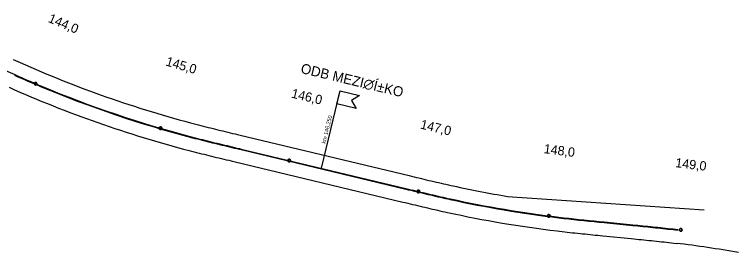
# Model space of a CAD drawing. Extents: x -670810 to -649614, y -1131928 to -1115069.
# Drawn here: x -655068 to -649614, y -1131928 to -1130133 of the extents above; entities that cross this region are included whole.
import ezdxf

# ---------------------------------------------------------------- set-up
doc = ezdxf.new("R2010")
doc.units = 0
for name, color, linetype in [('519 Var SK-4 Praporky stanic', 7, 'Continuous'), ('hranice_VRT_ZUR_Vysocina', 7, 'Continuous'), ('Situace - Osa koleje 2D', 7, 'Continuous'), ('Situace - Osa koleje tunel 2D', 7, 'Continuous'), ('Staničení - hlavní staničení + kolečka 1k', 7, 'Continuous')]:
    doc.layers.add(name, color=color, linetype=linetype)

# ---------------------------------------------------------------- blocks, each defined once
blk = doc.blocks.new('_U127')
at = {"layer": '519 Var SK-4 Praporky stanic'}
blk.add_line((-45.8, -299.9), (-45.8, 299.9), dxfattribs=at)
blk.add_lwpolyline([(-45.8, 299.9), (104.2, 299.9), (54.2, 249.9), (104.2, 199.9), (-45.8, 199.9)], close=True, dxfattribs=at)
blk.add_text('km 146,250', height=30, rotation=90, dxfattribs=at).set_placement((-59.2, -114))
blk = doc.blocks.new('_U126')
at = {"layer": '519 Var SK-4 Praporky stanic'}
blk.add_blockref('_U127', (45.8, -87.5), dxfattribs=at)
blk.add_text('ODB MEZI∅Í±KO', height=75, dxfattribs=at).set_placement((-325.1, 274.9))
blk = doc.blocks.new('Sit10Kruh_121')
at = {"layer": 'Staničení - hlavní staničení + kolečka 1k'}
blk.add_lwpolyline([(10, 0), (10, 0.6), (9.9, 1.3), (9.8, 1.9), (9.7, 2.5), (9.5, 3.1), (9.3, 3.7), (9, 4.3), (8.8, 4.8), (8.4, 5.4), (8.1, 5.9), (7.7, 6.4), (7.3, 6.8), (6.8, 7.3), (6.4, 7.7), (5.9, 8.1), (5.4, 8.4), (4.8, 8.8), (4.3, 9), (3.7, 9.3), (3.1, 9.5), (2.5, 9.7), (1.9, 9.8), (1.3, 9.9), (0.6, 10), (0, 10), (-0.6, 10), (-1.3, 9.9), (-1.9, 9.8), (-2.5, 9.7), (-3.1, 9.5), (-3.7, 9.3), (-4.3, 9), (-4.8, 8.8), (-5.4, 8.4), (-5.9, 8.1), (-6.4, 7.7), (-6.8, 7.3), (-7.3, 6.8), (-7.7, 6.4), (-8.1, 5.9), (-8.4, 5.4), (-8.8, 4.8), (-9, 4.3), (-9.3, 3.7), (-9.5, 3.1), (-9.7, 2.5), (-9.8, 1.9), (-9.9, 1.3), (-10, 0.6), (-10, 0), (-10, -0.6), (-9.9, -1.3), (-9.8, -1.9), (-9.7, -2.5), (-9.5, -3.1), (-9.3, -3.7), (-9, -4.3), (-8.8, -4.8), (-8.4, -5.4), (-8.1, -5.9), (-7.7, -6.4), (-7.3, -6.8), (-6.8, -7.3), (-6.4, -7.7), (-5.9, -8.1), (-5.4, -8.4), (-4.8, -8.8), (-4.3, -9), (-3.7, -9.3), (-3.1, -9.5), (-2.5, -9.7), (-1.9, -9.8), (-1.3, -9.9), (-0.6, -10), (0, -10), (0.6, -10), (1.3, -9.9), (1.9, -9.8), (2.5, -9.7), (3.1, -9.5), (3.7, -9.3), (4.3, -9), (4.8, -8.8), (5.4, -8.4), (5.9, -8.1), (6.4, -7.7), (6.8, -7.3), (7.3, -6.8), (7.7, -6.4), (8.1, -5.9), (8.4, -5.4), (8.8, -4.8), (9, -4.3), (9.3, -3.7), (9.5, -3.1), (9.7, -2.5), (9.8, -1.9), (9.9, -1.3)], close=True, dxfattribs=at)
blk.add_circle((0, 0), 10, dxfattribs=at)
blk = doc.blocks.new('Sit10Kruh_122')
at = {"layer": 'Staničení - hlavní staničení + kolečka 1k'}
blk.add_lwpolyline([(10, 0), (10, 0.6), (9.9, 1.3), (9.8, 1.9), (9.7, 2.5), (9.5, 3.1), (9.3, 3.7), (9, 4.3), (8.8, 4.8), (8.4, 5.4), (8.1, 5.9), (7.7, 6.4), (7.3, 6.8), (6.8, 7.3), (6.4, 7.7), (5.9, 8.1), (5.4, 8.4), (4.8, 8.8), (4.3, 9), (3.7, 9.3), (3.1, 9.5), (2.5, 9.7), (1.9, 9.8), (1.3, 9.9), (0.6, 10), (0, 10), (-0.6, 10), (-1.3, 9.9), (-1.9, 9.8), (-2.5, 9.7), (-3.1, 9.5), (-3.7, 9.3), (-4.3, 9), (-4.8, 8.8), (-5.4, 8.4), (-5.9, 8.1), (-6.4, 7.7), (-6.8, 7.3), (-7.3, 6.8), (-7.7, 6.4), (-8.1, 5.9), (-8.4, 5.4), (-8.8, 4.8), (-9, 4.3), (-9.3, 3.7), (-9.5, 3.1), (-9.7, 2.5), (-9.8, 1.9), (-9.9, 1.3), (-10, 0.6), (-10, 0), (-10, -0.6), (-9.9, -1.3), (-9.8, -1.9), (-9.7, -2.5), (-9.5, -3.1), (-9.3, -3.7), (-9, -4.3), (-8.8, -4.8), (-8.4, -5.4), (-8.1, -5.9), (-7.7, -6.4), (-7.3, -6.8), (-6.8, -7.3), (-6.4, -7.7), (-5.9, -8.1), (-5.4, -8.4), (-4.8, -8.8), (-4.3, -9), (-3.7, -9.3), (-3.1, -9.5), (-2.5, -9.7), (-1.9, -9.8), (-1.3, -9.9), (-0.6, -10), (0, -10), (0.6, -10), (1.3, -9.9), (1.9, -9.8), (2.5, -9.7), (3.1, -9.5), (3.7, -9.3), (4.3, -9), (4.8, -8.8), (5.4, -8.4), (5.9, -8.1), (6.4, -7.7), (6.8, -7.3), (7.3, -6.8), (7.7, -6.4), (8.1, -5.9), (8.4, -5.4), (8.8, -4.8), (9, -4.3), (9.3, -3.7), (9.5, -3.1), (9.7, -2.5), (9.8, -1.9), (9.9, -1.3)], close=True, dxfattribs=at)
blk.add_circle((0, 0), 10, dxfattribs=at)
blk = doc.blocks.new('Sit10Kruh_123')
at = {"layer": 'Staničení - hlavní staničení + kolečka 1k'}
blk.add_lwpolyline([(10, 0), (9.98026, 0.6279), (9.92114, 1.25334), (9.82288, 1.87382), (9.68584, 2.4869), (9.51056, 3.09016), (9.29776, 3.68124), (9.04828, 4.2578), (8.76306, 4.81754), (8.44328, 5.35826), (8.09016, 5.87786), (7.70514, 6.37424), (7.28968, 6.84548), (6.84548, 7.28968), (6.37424, 7.70514), (5.87786, 8.09016), (5.35826, 8.44328), (4.81754, 8.76306), (4.2578, 9.04828), (3.68124, 9.29776), (3.09016, 9.51056), (2.4869, 9.68584), (1.87382, 9.82288), (1.25334, 9.92114), (0.6279, 9.98026), (0, 10), (-0.6279, 9.98026), (-1.25334, 9.92114), (-1.87382, 9.82288), (-2.4869, 9.68584), (-3.09016, 9.51056), (-3.68124, 9.29776), (-4.2578, 9.04828), (-4.81754, 8.76306), (-5.35826, 8.44328), (-5.87786, 8.09016), (-6.37424, 7.70514), (-6.84548, 7.28968), (-7.28968, 6.84548), (-7.70514, 6.37424), (-8.09016, 5.87786), (-8.44328, 5.35826), (-8.76306, 4.81754), (-9.04828, 4.2578), (-9.29776, 3.68124), (-9.51056, 3.09016), (-9.68584, 2.4869), (-9.82288, 1.87382), (-9.92114, 1.25334), (-9.98026, 0.6279), (-10, 0), (-9.98026, -0.6279), (-9.92114, -1.25334), (-9.82288, -1.87382), (-9.68584, -2.4869), (-9.51056, -3.09016), (-9.29776, -3.68124), (-9.04828, -4.2578), (-8.76306, -4.81754), (-8.44328, -5.35826), (-8.09016, -5.87786), (-7.70514, -6.37424), (-7.28968, -6.84548), (-6.84548, -7.28968), (-6.37424, -7.70514), (-5.87786, -8.09016), (-5.35826, -8.44328), (-4.81754, -8.76306), (-4.2578, -9.04828), (-3.68124, -9.29776), (-3.09016, -9.51056), (-2.4869, -9.68584), (-1.87382, -9.82288), (-1.25334, -9.92114), (-0.6279, -9.98026), (0, -10), (0.6279, -9.98026), (1.25334, -9.92114), (1.87382, -9.82288), (2.4869, -9.68584), (3.09016, -9.51056), (3.68124, -9.29776), (4.2578, -9.04828), (4.81754, -8.76306), (5.35826, -8.44328), (5.87786, -8.09016), (6.37424, -7.70514), (6.84548, -7.28968), (7.28968, -6.84548), (7.70514, -6.37424), (8.09016, -5.87786), (8.44328, -5.35826), (8.76306, -4.81754), (9.04828, -4.2578), (9.29776, -3.68124), (9.51056, -3.09016), (9.68584, -2.4869), (9.82288, -1.87382), (9.92114, -1.25334)], close=True, dxfattribs=at)
blk.add_circle((0, 0), 10, dxfattribs=at)
blk = doc.blocks.new('Sit10Kruh_124')
at = {"layer": 'Staničení - hlavní staničení + kolečka 1k'}
blk.add_lwpolyline([(10, 0), (10, 0.6), (9.9, 1.3), (9.8, 1.9), (9.7, 2.5), (9.5, 3.1), (9.3, 3.7), (9, 4.3), (8.8, 4.8), (8.4, 5.4), (8.1, 5.9), (7.7, 6.4), (7.3, 6.8), (6.8, 7.3), (6.4, 7.7), (5.9, 8.1), (5.4, 8.4), (4.8, 8.8), (4.3, 9), (3.7, 9.3), (3.1, 9.5), (2.5, 9.7), (1.9, 9.8), (1.3, 9.9), (0.6, 10), (0, 10), (-0.6, 10), (-1.3, 9.9), (-1.9, 9.8), (-2.5, 9.7), (-3.1, 9.5), (-3.7, 9.3), (-4.3, 9), (-4.8, 8.8), (-5.4, 8.4), (-5.9, 8.1), (-6.4, 7.7), (-6.8, 7.3), (-7.3, 6.8), (-7.7, 6.4), (-8.1, 5.9), (-8.4, 5.4), (-8.8, 4.8), (-9, 4.3), (-9.3, 3.7), (-9.5, 3.1), (-9.7, 2.5), (-9.8, 1.9), (-9.9, 1.3), (-10, 0.6), (-10, 0), (-10, -0.6), (-9.9, -1.3), (-9.8, -1.9), (-9.7, -2.5), (-9.5, -3.1), (-9.3, -3.7), (-9, -4.3), (-8.8, -4.8), (-8.4, -5.4), (-8.1, -5.9), (-7.7, -6.4), (-7.3, -6.8), (-6.8, -7.3), (-6.4, -7.7), (-5.9, -8.1), (-5.4, -8.4), (-4.8, -8.8), (-4.3, -9), (-3.7, -9.3), (-3.1, -9.5), (-2.5, -9.7), (-1.9, -9.8), (-1.3, -9.9), (-0.6, -10), (0, -10), (0.6, -10), (1.3, -9.9), (1.9, -9.8), (2.5, -9.7), (3.1, -9.5), (3.7, -9.3), (4.3, -9), (4.8, -8.8), (5.4, -8.4), (5.9, -8.1), (6.4, -7.7), (6.8, -7.3), (7.3, -6.8), (7.7, -6.4), (8.1, -5.9), (8.4, -5.4), (8.8, -4.8), (9, -4.3), (9.3, -3.7), (9.5, -3.1), (9.7, -2.5), (9.8, -1.9), (9.9, -1.3)], close=True, dxfattribs=at)
blk.add_circle((0, 0), 10, dxfattribs=at)
blk = doc.blocks.new('Sit10Kruh_125')
at = {"layer": 'Staničení - hlavní staničení + kolečka 1k'}
blk.add_lwpolyline([(10, 0), (9.98026, 0.6279), (9.92114, 1.25334), (9.82288, 1.87382), (9.68584, 2.4869), (9.51056, 3.09016), (9.29776, 3.68124), (9.04828, 4.2578), (8.76306, 4.81754), (8.44328, 5.35826), (8.09016, 5.87786), (7.70514, 6.37424), (7.28968, 6.84548), (6.84548, 7.28968), (6.37424, 7.70514), (5.87786, 8.09016), (5.35826, 8.44328), (4.81754, 8.76306), (4.2578, 9.04828), (3.68124, 9.29776), (3.09016, 9.51056), (2.4869, 9.68584), (1.87382, 9.82288), (1.25334, 9.92114), (0.6279, 9.98026), (0, 10), (-0.6279, 9.98026), (-1.25334, 9.92114), (-1.87382, 9.82288), (-2.4869, 9.68584), (-3.09016, 9.51056), (-3.68124, 9.29776), (-4.2578, 9.04828), (-4.81754, 8.76306), (-5.35826, 8.44328), (-5.87786, 8.09016), (-6.37424, 7.70514), (-6.84548, 7.28968), (-7.28968, 6.84548), (-7.70514, 6.37424), (-8.09016, 5.87786), (-8.44328, 5.35826), (-8.76306, 4.81754), (-9.04828, 4.2578), (-9.29776, 3.68124), (-9.51056, 3.09016), (-9.68584, 2.4869), (-9.82288, 1.87382), (-9.92114, 1.25334), (-9.98026, 0.6279), (-10, 0), (-9.98026, -0.6279), (-9.92114, -1.25334), (-9.82288, -1.87382), (-9.68584, -2.4869), (-9.51056, -3.09016), (-9.29776, -3.68124), (-9.04828, -4.2578), (-8.76306, -4.81754), (-8.44328, -5.35826), (-8.09016, -5.87786), (-7.70514, -6.37424), (-7.28968, -6.84548), (-6.84548, -7.28968), (-6.37424, -7.70514), (-5.87786, -8.09016), (-5.35826, -8.44328), (-4.81754, -8.76306), (-4.2578, -9.04828), (-3.68124, -9.29776), (-3.09016, -9.51056), (-2.4869, -9.68584), (-1.87382, -9.82288), (-1.25334, -9.92114), (-0.6279, -9.98026), (0, -10), (0.6279, -9.98026), (1.25334, -9.92114), (1.87382, -9.82288), (2.4869, -9.68584), (3.09016, -9.51056), (3.68124, -9.29776), (4.2578, -9.04828), (4.81754, -8.76306), (5.35826, -8.44328), (5.87786, -8.09016), (6.37424, -7.70514), (6.84548, -7.28968), (7.28968, -6.84548), (7.70514, -6.37424), (8.09016, -5.87786), (8.44328, -5.35826), (8.76306, -4.81754), (9.04828, -4.2578), (9.29776, -3.68124), (9.51056, -3.09016), (9.68584, -2.4869), (9.82288, -1.87382), (9.92114, -1.25334)], close=True, dxfattribs=at)
blk.add_circle((0, 0), 10, dxfattribs=at)
blk = doc.blocks.new('Sit10Kruh_126')
at = {"layer": 'Staničení - hlavní staničení + kolečka 1k'}
blk.add_lwpolyline([(10, 0), (9.98026, 0.6279), (9.92114, 1.25334), (9.82288, 1.87382), (9.68584, 2.4869), (9.51056, 3.09016), (9.29776, 3.68124), (9.04828, 4.2578), (8.76306, 4.81754), (8.44328, 5.35826), (8.09016, 5.87786), (7.70514, 6.37424), (7.28968, 6.84548), (6.84548, 7.28968), (6.37424, 7.70514), (5.87786, 8.09016), (5.35826, 8.44328), (4.81754, 8.76306), (4.2578, 9.04828), (3.68124, 9.29776), (3.09016, 9.51056), (2.4869, 9.68584), (1.87382, 9.82288), (1.25334, 9.92114), (0.6279, 9.98026), (0, 10), (-0.6279, 9.98026), (-1.25334, 9.92114), (-1.87382, 9.82288), (-2.4869, 9.68584), (-3.09016, 9.51056), (-3.68124, 9.29776), (-4.2578, 9.04828), (-4.81754, 8.76306), (-5.35826, 8.44328), (-5.87786, 8.09016), (-6.37424, 7.70514), (-6.84548, 7.28968), (-7.28968, 6.84548), (-7.70514, 6.37424), (-8.09016, 5.87786), (-8.44328, 5.35826), (-8.76306, 4.81754), (-9.04828, 4.2578), (-9.29776, 3.68124), (-9.51056, 3.09016), (-9.68584, 2.4869), (-9.82288, 1.87382), (-9.92114, 1.25334), (-9.98026, 0.6279), (-10, 0), (-9.98026, -0.6279), (-9.92114, -1.25334), (-9.82288, -1.87382), (-9.68584, -2.4869), (-9.51056, -3.09016), (-9.29776, -3.68124), (-9.04828, -4.2578), (-8.76306, -4.81754), (-8.44328, -5.35826), (-8.09016, -5.87786), (-7.70514, -6.37424), (-7.28968, -6.84548), (-6.84548, -7.28968), (-6.37424, -7.70514), (-5.87786, -8.09016), (-5.35826, -8.44328), (-4.81754, -8.76306), (-4.2578, -9.04828), (-3.68124, -9.29776), (-3.09016, -9.51056), (-2.4869, -9.68584), (-1.87382, -9.82288), (-1.25334, -9.92114), (-0.6279, -9.98026), (0, -10), (0.6279, -9.98026), (1.25334, -9.92114), (1.87382, -9.82288), (2.4869, -9.68584), (3.09016, -9.51056), (3.68124, -9.29776), (4.2578, -9.04828), (4.81754, -8.76306), (5.35826, -8.44328), (5.87786, -8.09016), (6.37424, -7.70514), (6.84548, -7.28968), (7.28968, -6.84548), (7.70514, -6.37424), (8.09016, -5.87786), (8.44328, -5.35826), (8.76306, -4.81754), (9.04828, -4.2578), (9.29776, -3.68124), (9.51056, -3.09016), (9.68584, -2.4869), (9.82288, -1.87382), (9.92114, -1.25334)], close=True, dxfattribs=at)
blk.add_circle((0, 0), 10, dxfattribs=at)

msp = doc.modelspace()

# ---------------------------------------------------------------- linework, layer by layer
at = {"layer": 'hranice_VRT_ZUR_Vysocina'}
msp.add_line((-651354.2, -1131505), (-649873.6, -1131607.5), dxfattribs=at)
for points in [[(-655077.3, -1130471.9), (-655060.1, -1130479.8), (-655042.9, -1130487.5), (-655025.6, -1130495.3), (-655025.7, -1130495.3)], [(-653701, -1130961), (-653701.1, -1130961), (-653682.8, -1130965.8), (-653664.5, -1130970.5), (-653646.1, -1130975.2), (-653627.8, -1130979.8), (-653609.5, -1130984.4), (-653591.1, -1130989), (-653572.7, -1130993.6), (-653554.3, -1130998.1), (-653535.8, -1131002.6), (-653517.3, -1131007.1), (-653498.8, -1131011.6), (-653480.3, -1131016.1), (-653461.8, -1131020.5), (-653443.3, -1131025), (-653424.7, -1131029.4), (-653406.1, -1131033.9), (-653387.5, -1131038.3), (-653369, -1131042.8), (-652095.6, -1131348.3), (-652077, -1131352.7), (-652058.4, -1131357.2), (-652039.8, -1131361.6), (-652021.3, -1131366.1), (-652002.7, -1131370.5), (-651984.2, -1131375), (-651965.7, -1131379.4), (-651947.1, -1131383.8), (-651928.6, -1131388.1), (-651910.2, -1131392.5), (-651891.7, -1131396.8), (-651873.2, -1131401.1), (-651854.8, -1131405.4), (-651836.3, -1131409.6), (-651817.9, -1131413.8), (-651799.4, -1131417.9), (-651781, -1131422), (-651762.4, -1131426.1), (-651762.5, -1131426.1)], [(-653752.7, -1131159.1), (-653752.6, -1131159.1), (-653734, -1131164), (-653715.3, -1131168.8), (-653696.6, -1131173.6), (-653677.8, -1131178.3), (-653659.1, -1131183), (-653640.4, -1131187.7), (-653621.7, -1131192.3), (-653603, -1131196.9), (-653584.3, -1131201.5), (-653565.6, -1131206), (-653547, -1131210.5), (-653528.3, -1131215), (-653509.7, -1131219.5), (-653491.1, -1131224), (-653472.5, -1131228.5), (-653453.9, -1131232.9), (-653435.3, -1131237.4), (-653416.7, -1131241.9), (-652143.4, -1131547.3), (-652124.8, -1131551.8), (-652106.2, -1131556.2), (-652087.6, -1131560.7), (-652069, -1131565.1), (-652050.3, -1131569.6), (-652031.7, -1131574.1), (-652013, -1131578.5), (-651994.4, -1131582.9), (-651975.7, -1131587.4), (-651956.9, -1131591.8), (-651938.2, -1131596.2), (-651919.4, -1131600.5), (-651900.6, -1131604.9), (-651881.8, -1131609.2), (-651863, -1131613.4), (-651844.1, -1131617.7), (-651825.2, -1131621.9), (-651806.5, -1131626), (-651806.4, -1131626)], [(-650980.4, -1131765.5), (-650980.3, -1131765.5), (-650961.2, -1131767.8), (-650942, -1131770), (-650922.8, -1131772.2), (-650903.6, -1131774.4), (-650884.4, -1131776.5), (-650865.2, -1131778.6), (-650846.1, -1131780.6), (-650826.9, -1131782.6), (-650807.8, -1131784.6), (-650788.7, -1131786.6), (-650769.6, -1131788.5), (-650750.5, -1131790.4), (-650731.4, -1131792.4), (-650712.4, -1131794.3), (-650693.3, -1131796.2), (-650674.3, -1131798.1), (-650655.3, -1131799.9), (-650636.2, -1131801.8), (-650421.2, -1131823.2), (-650402.2, -1131825.1), (-650383.2, -1131827), (-650364.2, -1131828.9), (-650345.2, -1131830.8), (-650326.2, -1131832.7), (-650307.2, -1131834.6), (-650288.3, -1131836.5), (-650269.4, -1131838.5), (-650250.4, -1131840.4), (-650231.6, -1131842.4), (-650212.7, -1131844.3), (-650193.8, -1131846.4), (-650175, -1131848.4), (-650156.2, -1131850.5), (-650137.4, -1131852.6), (-650118.6, -1131854.7), (-650099.9, -1131856.9), (-650081, -1131859.1), (-650081.1, -1131859.1)]]:
    msp.add_lwpolyline(points, dxfattribs=at)
for centre, radius, start, end in [((-651553.4, -1122736.8), 8500, 245.8891, 255.36477), ((-651553.4, -1122736.9), 8704.6, 245.88876, 255.36511), ((-649945.5, -1123122.4), 8500.1, 257.65663, 260.46031), ((-649945.5, -1123122.5), 8704.7, 257.65629, 263.17189), ((-651091.7, -1140298.8), 8500, 79.98571, 83.17162)]:
    msp.add_arc(centre, radius, start, end, dxfattribs=at)
at = {"layer": 'Situace - Osa koleje 2D'}
for p, q in [((-653393.3, -1131144.6), (-653373.5, -1131149.4)), ((-653392.3, -1131140), (-653372.4, -1131144.8)), ((-653361.4, -1131152.3), (-652120, -1131450.1)), ((-653360.3, -1131147.7), (-652118.9, -1131445.5)), ((-650626.3, -1131702.3), (-650411.3, -1131723.7)), ((-650625.9, -1131697.7), (-650410.9, -1131719))]:
    msp.add_line(p, q, dxfattribs=at)
for points in [[(-653727.4, -1131062.4), (-653708.9, -1131067.2), (-653690.4, -1131071.9), (-653671.9, -1131076.7), (-653653.4, -1131081.4), (-653634.8, -1131086), (-653616.3, -1131090.6), (-653597.7, -1131095.2), (-653579.2, -1131099.8), (-653560.6, -1131104.3), (-653542, -1131108.8), (-653523.4, -1131113.4), (-653504.9, -1131117.8), (-653486.3, -1131122.3), (-653467.7, -1131126.8), (-653449.1, -1131131.2), (-653430.5, -1131135.7), (-653411.9, -1131140.2), (-653393.3, -1131144.6)], [(-653726.3, -1131057.8), (-653707.8, -1131062.6), (-653689.3, -1131067.4), (-653670.8, -1131072.1), (-653652.3, -1131076.8), (-653633.7, -1131081.4), (-653615.2, -1131086.1), (-653596.6, -1131090.7), (-653578.1, -1131095.2), (-653559.5, -1131099.8), (-653540.9, -1131104.3), (-653522.4, -1131108.8), (-653503.8, -1131113.3), (-653485.2, -1131117.7), (-653466.6, -1131122.2), (-653448, -1131126.7), (-653429.5, -1131131.1), (-653410.9, -1131135.6), (-653392.3, -1131140)], [(-652118.9, -1131445.5), (-652100.3, -1131450), (-652081.7, -1131454.4), (-652063.1, -1131458.9), (-652044.6, -1131463.3), (-652026, -1131467.8), (-652007.4, -1131472.2), (-651988.8, -1131476.7), (-651970.2, -1131481.1), (-651951.6, -1131485.5), (-651933, -1131489.8), (-651914.4, -1131494.2), (-651895.8, -1131498.5), (-651877.2, -1131502.8), (-651858.5, -1131507.1), (-651839.9, -1131511.3), (-651821.2, -1131515.5), (-651802.6, -1131519.6), (-651783.9, -1131523.7)], [(-652120, -1131450.1), (-652101.5, -1131454.5), (-652082.9, -1131459), (-652064.3, -1131463.4), (-652045.7, -1131467.9), (-652027.1, -1131472.3), (-652008.5, -1131476.8), (-651989.9, -1131481.2), (-651971.3, -1131485.6), (-651952.7, -1131490), (-651934.1, -1131494.4), (-651915.5, -1131498.8), (-651896.9, -1131503.1), (-651878.2, -1131507.4), (-651859.6, -1131511.7), (-651841, -1131515.9), (-651822.3, -1131520.1), (-651803.6, -1131524.2), (-651785, -1131528.3)], [(-650968.5, -1131666.2), (-650949.5, -1131668.5), (-650930.5, -1131670.7), (-650911.6, -1131672.8), (-650892.6, -1131675), (-650873.6, -1131677.1), (-650854.6, -1131679.1), (-650835.5, -1131681.2), (-650816.5, -1131683.2), (-650797.5, -1131685.1), (-650778.5, -1131687.1), (-650759.5, -1131689), (-650740.5, -1131690.9), (-650721.4, -1131692.9), (-650702.4, -1131694.8), (-650683.4, -1131696.7), (-650664.4, -1131698.5), (-650645.4, -1131700.4), (-650626.3, -1131702.3)], [(-650968, -1131661.5), (-650949, -1131663.8), (-650930, -1131666), (-650911.1, -1131668.2), (-650892.1, -1131670.3), (-650873.1, -1131672.4), (-650854.1, -1131674.4), (-650835.1, -1131676.5), (-650816.1, -1131678.5), (-650797.1, -1131680.5), (-650778, -1131682.4), (-650759, -1131684.3), (-650740, -1131686.3), (-650721, -1131688.2), (-650702, -1131690.1), (-650683, -1131692), (-650663.9, -1131693.9), (-650644.9, -1131695.8), (-650625.9, -1131697.7)], [(-650410.9, -1131719), (-650391.9, -1131720.9), (-650372.8, -1131722.8), (-650353.8, -1131724.7), (-650334.8, -1131726.6), (-650315.8, -1131728.5), (-650296.8, -1131730.4), (-650277.7, -1131732.4), (-650258.7, -1131734.3), (-650239.7, -1131736.3), (-650220.7, -1131738.2), (-650201.7, -1131740.2), (-650182.7, -1131742.3), (-650163.7, -1131744.3), (-650144.7, -1131746.4), (-650125.7, -1131748.5), (-650106.7, -1131750.7), (-650087.7, -1131752.9), (-650068.7, -1131755.2)], [(-650411.3, -1131723.7), (-650392.3, -1131725.6), (-650373.3, -1131727.5), (-650354.3, -1131729.4), (-650335.2, -1131731.3), (-650316.2, -1131733.2), (-650297.2, -1131735.1), (-650278.2, -1131737), (-650259.2, -1131739), (-650240.2, -1131740.9), (-650221.2, -1131742.9), (-650202.2, -1131744.9), (-650183.2, -1131746.9), (-650164.2, -1131749), (-650145.2, -1131751.1), (-650126.2, -1131753.2), (-650107.2, -1131755.4), (-650088.2, -1131757.6), (-650069.2, -1131759.8)]]:
    msp.add_lwpolyline(points, dxfattribs=at)
for centre, radius, start, end in [((-651553.4, -1122736.8), 8604.7, 247.34887, 255.36508), ((-651553.4, -1122736.8), 8600, 247.34887, 255.36477), ((-649945.5, -1123122.5), 8604.7, 257.65628, 263.1719), ((-649945.5, -1123122.5), 8600, 257.6566, 263.17158)]:
    msp.add_arc(centre, radius, start, end, dxfattribs=at)
at = {"layer": 'Situace - Osa koleje tunel 2D'}
for p, q in [((-653373.5, -1131149.4), (-653361.4, -1131152.3)), ((-653372.4, -1131144.8), (-653360.3, -1131147.7))]:
    msp.add_line(p, q, dxfattribs=at)
msp.add_lwpolyline([(-655378.5, -1130441.6), (-655361.2, -1130449.8), (-655343.9, -1130457.9), (-655326.7, -1130466.1), (-655309.4, -1130474.2), (-655292.1, -1130482.4), (-655274.8, -1130490.5), (-655257.5, -1130498.7), (-655240.2, -1130506.8), (-655222.9, -1130514.9), (-655205.6, -1130522.9), (-655188.2, -1130531), (-655170.9, -1130539), (-655153.5, -1130547), (-655136.2, -1130555), (-655118.8, -1130562.9), (-655101.4, -1130570.9), (-655084, -1130578.7), (-655066.5, -1130586.5)], dxfattribs=at)
for radius, start in [(8604.7, 245.88879), (8600, 245.8891)]:
    msp.add_arc((-651553.4, -1122736.8), radius, start, 247.34887, dxfattribs=at)

# ---------------------------------------------------------------- block references
at = {"layer": '519 Var SK-4 Praporky stanic', "rotation": -13.489318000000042}
msp.add_blockref('_U126', (-652665.2, -1130916), dxfattribs=at)
at = {"layer": 'Staničení - hlavní staničení + kolečka 1k'}
for name, p, rotation in [('Sit10Kruh_121', (-654909.3, -1130655.1), -22.96803799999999), ('Sit10Kruh_122', (-653968, -1130990.9), -16.30573799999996), ('Sit10Kruh_123', (-652998.2, -1131234.6), -13.489318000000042), ('Sit10Kruh_124', (-652025.8, -1131467.8), -13.446778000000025), ('Sit10Kruh_125', (-651043.5, -1131652.2), -7.335042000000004), ('Sit10Kruh_126', (-650049.1, -1131757.5), -6.9597860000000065)]:
    msp.add_blockref(name, p, dxfattribs=dict(at, rotation=rotation))

# ---------------------------------------------------------------- texts
for s, rotation, p in [('144,0', 337.0319, (-654820.1, -1130187.8)), ('145,0', 343.6942, (-653933.6, -1130516.5)), ('146,0', 346.5107, (-652987.2, -1130759)), ('147,0', 346.5532, (-652015.2, -1130992.3)), ('148,0', 352.665, (-651083.5, -1131178.2)), ('149,0', 353.0402, (-650092.2, -1131283.8))]:
    msp.add_text(s, height=70, rotation=rotation, dxfattribs=at).set_placement(p)

doc.saveas('drawing.dxf')
